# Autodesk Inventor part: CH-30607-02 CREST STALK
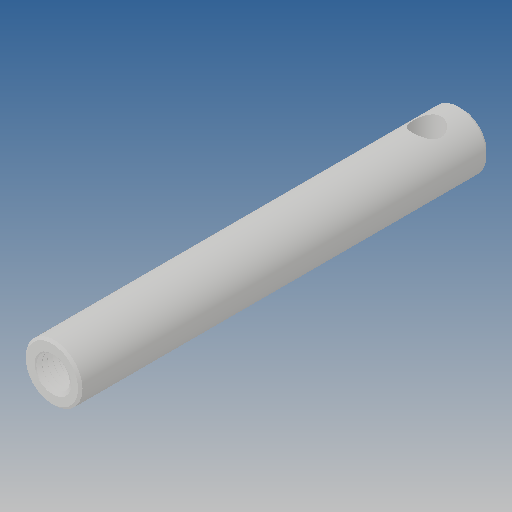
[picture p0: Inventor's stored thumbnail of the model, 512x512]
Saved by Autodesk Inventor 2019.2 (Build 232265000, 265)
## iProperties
Created: 2012-09
Part Number: CH-30607-02 CREST STALK
Material: Ogólny
Document SubType Name: Modeling
Designer: CADENGINEERING4
Density: 1 g/cm^3
Appearance: Domyślna
Author: CADENGINEERING4
Revision Number: ÈÎºÎ
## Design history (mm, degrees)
feature "ÇÐ³ý-É¨Ãè1"
node "Bryła1"
